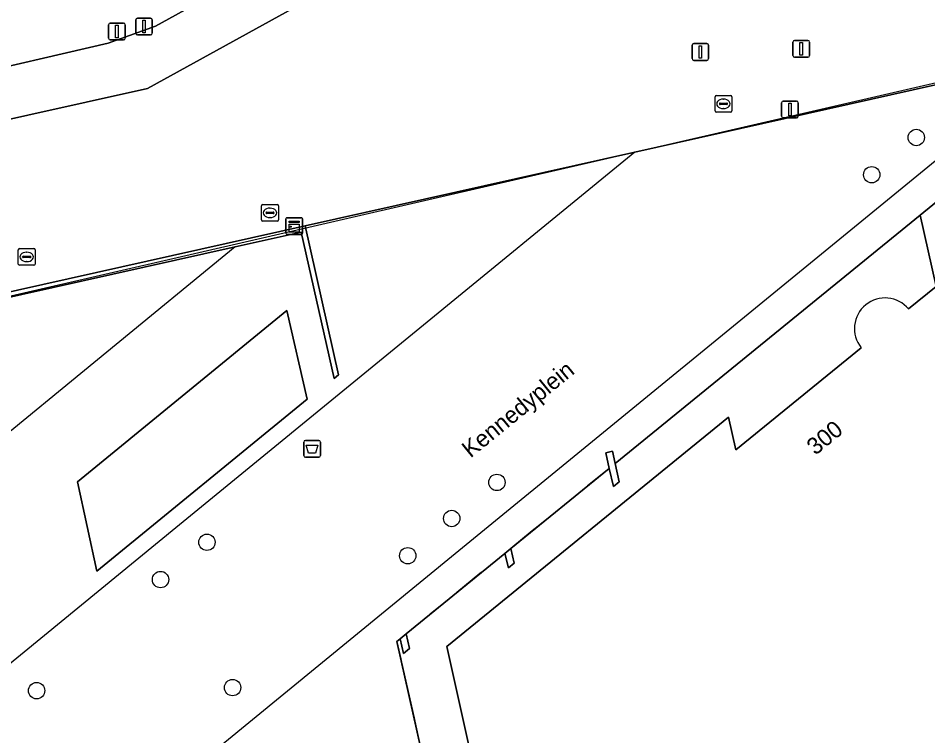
# Model space of a CAD drawing. Extents: x 160806 to 161707, y 383696 to 384148.
# Drawn here: x 161489.3 to 161543.6, y 383912.2 to 383955 of the extents above; entities that cross this region are included whole.
import ezdxf

# ---------------------------------------------------------------- set-up
doc = ezdxf.new("R2010")
doc.units = 0
for name, color, linetype in [('IMGEO_Afvalbak', 7, 'Continuous'), ('IMGEO_Berm_open', 7, 'Continuous'), ('IMGEO_Boom', 7, 'Continuous'), ('IMGEO_Drukknoppaal', 7, 'Continuous'), ('IMGEO_Kast', 7, 'Continuous'), ('IMGEO_Kolk', 7, 'Continuous'), ('IMGEO_Lijnafwatering', 7, 'Continuous'), ('IMGEO_Muur', 7, 'Continuous'), ('IMGEO_Openbare_ruimte_label', 7, 'Continuous'), ('IMGEO_Pand', 7, 'Continuous'), ('IMGEO_Pand_nummerreeks', 7, 'Continuous'), ('IMGEO_Pand_overbouw', 7, 'Continuous'), ('IMGEO_Rijbaan_lokaal_gesloten', 7, 'Continuous'), ('IMGEO_Rioolput', 7, 'Continuous'), ('IMGEO_Verkeersregelinstallatiepaal', 7, 'Continuous'), ('IMGEO_Voetgangersgebied_open', 7, 'Continuous'), ('IMGEO_Voetpad_open', 7, 'Continuous')]:
    doc.layers.add(name, color=color, linetype=linetype)

msp = doc.modelspace()

# ---------------------------------------------------------------- linework, layer by layer
at = {"layer": 'IMGEO_Afvalbak'}
for p, q in [((161506.372, 383928.933), (161506.372, 383929.733)), ((161506.372, 383929.733), (161506.372, 383928.933)), ((161506.472, 383929.833), (161507.262, 383929.833)), ((161507.262, 383929.833), (161506.472, 383929.833)), ((161507.362, 383929.733), (161507.362, 383928.933)), ((161507.362, 383928.933), (161507.362, 383929.733)), ((161507.262, 383928.833), (161506.472, 383928.833)), ((161506.472, 383928.833), (161507.262, 383928.833))]:
    msp.add_line(p, q, dxfattribs=at)
msp.add_lwpolyline([(161506.515, 383929.547), (161507.219, 383929.547), (161507.07, 383929.077), (161506.664, 383929.077), (161506.515, 383929.547)], dxfattribs=at)
for centre, start, end in [((161506.472, 383929.733), 90, 180), ((161506.472, 383929.733), 90, 180), ((161507.262, 383929.733), 0, 90), ((161507.262, 383929.733), 360, 90), ((161506.472, 383928.933), 180, 270), ((161506.472, 383928.933), 180, 270), ((161507.262, 383928.933), 270, 0), ((161507.262, 383928.933), 270, 0)]:
    msp.add_arc(centre, 0.1, start, end, dxfattribs=at)
at = {"layer": 'IMGEO_Berm_open'}
msp.add_lwpolyline([(161482.764, 383950.802), (161484.817, 383951.25), (161485.579, 383951.426), (161494.69, 383953.527), (161497.52, 383954.56), (161515.493, 383964.453)], dxfattribs=at)
at = {"layer": 'IMGEO_Boom'}
for centre in [(161542.926, 383947.907), (161540.266, 383945.685), (161517.898, 383927.324), (161515.202, 383925.175), (161500.593, 383923.754), (161512.579, 383922.952), (161497.824, 383921.531), (161502.123, 383915.083), (161490.429, 383914.901)]:
    msp.add_circle(centre, 0.489, dxfattribs=at)
at = {"layer": 'IMGEO_Drukknoppaal'}
for p, q in [((161496.34, 383954.127), (161496.34, 383954.927)), ((161496.34, 383954.927), (161496.34, 383954.127)), ((161496.44, 383955.027), (161497.23, 383955.027)), ((161497.23, 383955.027), (161496.44, 383955.027)), ((161497.33, 383954.927), (161497.33, 383954.127)), ((161497.33, 383954.127), (161497.33, 383954.927)), ((161497.23, 383954.027), (161496.44, 383954.027)), ((161496.44, 383954.027), (161497.23, 383954.027))]:
    msp.add_line(p, q, dxfattribs=at)
msp.add_lwpolyline([(161496.76, 383954.902), (161496.91, 383954.902), (161496.91, 383954.152), (161496.76, 383954.152), (161496.76, 383954.902)], dxfattribs=at)
for centre, start, end in [((161496.44, 383954.927), 90, 180), ((161496.44, 383954.927), 90, 180), ((161497.23, 383954.927), 0, 90), ((161497.23, 383954.927), 360, 90), ((161496.44, 383954.127), 180, 270), ((161496.44, 383954.127), 180, 270), ((161497.23, 383954.127), 270, 0), ((161497.23, 383954.127), 270, 0)]:
    msp.add_arc(centre, 0.1, start, end, dxfattribs=at)
at = {"layer": 'IMGEO_Kast'}
for p, q in [((161505.305, 383942.198), (161505.305, 383943.039)), ((161505.305, 383943.039), (161505.305, 383942.198)), ((161505.38, 383943.123), (161506.221, 383943.123)), ((161506.221, 383943.123), (161505.38, 383943.123)), ((161506.305, 383943.048), (161506.305, 383942.207)), ((161506.305, 383942.207), (161506.305, 383943.048)), ((161506.23, 383942.123), (161505.389, 383942.123)), ((161505.389, 383942.123), (161506.23, 383942.123))]:
    msp.add_line(p, q, dxfattribs=at)
for points in [[(161505.5, 383942.913), (161506.1, 383942.913), (161506.1, 383942.828), (161505.5, 383942.828), (161505.5, 383942.913)], [(161505.5, 383942.738), (161506.1, 383942.738), (161506.1, 383942.249), (161505.5, 383942.249), (161505.5, 383942.738)]]:
    msp.add_lwpolyline(points, dxfattribs=at)
msp.add_circle((161505.584, 383942.587), 0.0377, dxfattribs=at)
for centre, start, end in [((161505.383, 383943.045), 92.4484, 184.2845), ((161505.383, 383943.045), 92.4484, 184.2845), ((161506.227, 383943.045), 2.4484, 94.2845), ((161506.227, 383943.045), 2.4484, 94.2845), ((161505.383, 383942.201), 182.4484, 274.2845), ((161505.383, 383942.201), 182.4484, 274.2845), ((161506.227, 383942.201), 272.4484, 4.2845), ((161506.227, 383942.201), 272.4484, 4.2845)]:
    msp.add_arc(centre, 0.0779, start, end, dxfattribs=at)
at = {"layer": 'IMGEO_Kolk'}
for p, q in [((161503.856, 383942.985), (161503.856, 383943.837)), ((161503.931, 383943.911), (161504.783, 383943.911)), ((161504.857, 383943.837), (161504.857, 383942.985)), ((161504.115, 383943.405), (161504.115, 383943.417)), ((161504.553, 383943.368), (161504.155, 383943.368)), ((161504.158, 383943.454), (161504.556, 383943.454)), ((161504.344, 383943.691), (161504.369, 383943.691)), ((161504.599, 383943.417), (161504.599, 383943.405)), ((161504.783, 383942.911), (161503.931, 383942.911)), ((161504.367, 383943.131), (161504.342, 383943.131))]:
    msp.add_line(p, q, dxfattribs=at)
for points in [[(161503.856, 383942.985), (161503.856, 383943.837)], [(161503.931, 383943.911), (161504.783, 383943.911)], [(161504.857, 383943.837), (161504.857, 383942.985)], [(161504.783, 383942.911), (161503.931, 383942.911)]]:
    msp.add_lwpolyline(points, dxfattribs=at)
for centre, radius, start, end in [((161503.933, 383943.835), 0.0765, 91.552, 178.448), ((161503.933, 383943.835), 0.0765, 91.552, 178.448), ((161504.781, 383943.835), 0.0765, 1.552, 88.448), ((161504.781, 383943.835), 0.0765, 1.552, 88.448), ((161504.155, 383943.414), 0.0403, 85.8775, 175.7526), ((161504.152, 383943.404), 0.0366, 178.938, 274.7102), ((161504.556, 383943.411), 0.043, 264.8664, 352.4533), ((161504.56, 383943.416), 0.0386, 1.7309, 96.639), ((161503.933, 383942.987), 0.0765, 181.552, 268.448), ((161503.933, 383942.987), 0.0765, 181.552, 268.448), ((161504.781, 383942.987), 0.0765, 271.552, 358.448), ((161504.781, 383942.987), 0.0765, 271.552, 358.448)]:
    msp.add_arc(centre, radius, start, end, dxfattribs=at)
for centre, major_axis, ratio, start_param, end_param in [((161504.343, 383943.411), (-0.387, 0.002), 0.722429, 4.712389, 7.853982), ((161504.368, 383943.411), (-0.39, 0.002), 0.717154, 1.570796, 4.712389)]:
    msp.add_ellipse(centre, major_axis=major_axis, ratio=ratio, start_param=start_param, end_param=end_param, dxfattribs=at)
at = {"layer": 'IMGEO_Lijnafwatering'}
for points in [[(161551.704, 383952.753), (161533.558, 383937.906)], [(161526.128, 383947.032), (161512.429, 383935.821)], [(161502.28, 383941.387), (161486.939, 383928.817)], [(161533.558, 383937.906), (161515.412, 383923.059)], [(161512.429, 383935.821), (161498.731, 383924.609)], [(161498.731, 383924.609), (161485.032, 383913.398)], [(161515.412, 383923.059), (161497.266, 383908.212)]]:
    msp.add_lwpolyline(points, dxfattribs=at)
at = {"layer": 'IMGEO_Muur'}
msp.add_lwpolyline([(161454.756, 383931.084), (161454.819, 383930.799), (161476.856, 383935.709), (161477.167, 383934.318), (161484.378, 383936.019), (161484.102, 383937.319), (161502.28, 383941.387), (161506.222, 383942.268), (161508.183, 383933.535), (161508.439, 383933.738), (161506.454, 383942.63)], close=True, dxfattribs=at)
at = {"layer": 'IMGEO_Pand'}
msp.add_lwpolyline([(161539.638, 383935.367), (161532.156, 383929.275), (161531.72, 383931.221), (161514.903, 383917.532), (161521.152, 383889.432), (161518.425, 383888.826), (161522.234, 383871.748), (161522.889, 383868.814), (161526.561, 383852.352), (161548.06, 383857.157), (161555.04, 383858.718), (161562.148, 383860.307), (161569.113, 383861.863), (161576.544, 383863.524), (161577.028, 383863.632), (161563.33, 383924.497), (161562.871, 383924.395), (161556.299, 383953.974), (161555.972, 383953.708), (161543.162, 383943.281), (161544.114, 383939.013), (161542.463, 383937.675)], dxfattribs=at)
for points in [[(161524.849, 383927.077), (161525.203, 383927.357), (161524.957, 383928.451), (161524.791, 383929.187), (161524.393, 383929.092), (161524.603, 383928.164)], [(161518.585, 383922.232), (161518.924, 383922.501), (161518.722, 383923.384), (161518.377, 383923.091)], [(161512.128, 383917.99), (161512.33, 383917.119), (161512.682, 383917.413), (161512.48, 383918.284)]]:
    msp.add_lwpolyline(points, close=True, dxfattribs=at)
msp.add_arc((161541.06, 383936.509), 1.824, 39.719, 218.778, dxfattribs=at)
at = {"layer": 'IMGEO_Pand_overbouw'}
msp.add_lwpolyline([(161576.544, 383863.524), (161556.299, 383953.974), (161403.923, 383918.874), (161417.58, 383859.039), (161456.542, 383836.683)], close=True, dxfattribs=at)
for points in [[(161542.463, 383937.675), (161544.114, 383939.013), (161543.162, 383943.281), (161524.957, 383928.451), (161525.203, 383927.357), (161524.849, 383927.077), (161524.603, 383928.164), (161523.307, 383927.113), (161523.125, 383926.96), (161521.751, 383925.839), (161521.569, 383925.688), (161520.187, 383924.579), (161520.009, 383924.429), (161518.722, 383923.384), (161518.924, 383922.501), (161518.585, 383922.232), (161518.377, 383923.091), (161517.073, 383922.029), (161516.886, 383921.882), (161515.513, 383920.754), (161515.329, 383920.601), (161513.944, 383919.481), (161513.761, 383919.329), (161512.48, 383918.284), (161512.682, 383917.413), (161512.33, 383917.119), (161512.128, 383917.99)], [(161521.152, 383889.432), (161514.903, 383917.532), (161531.72, 383931.221), (161532.156, 383929.275), (161539.638, 383935.367)], [(161512.128, 383917.99), (161511.932, 383917.834), (161512.164, 383916.794), (161512.207, 383916.608), (161512.559, 383915.03), (161512.602, 383914.843), (161512.953, 383913.273), (161512.995, 383913.087), (161513.344, 383911.529)]]:
    msp.add_lwpolyline(points, dxfattribs=at)
msp.add_arc((161541.06, 383936.509), 1.824, 39.719, 218.778, dxfattribs=at)
at = {"layer": 'IMGEO_Rijbaan_lokaal_gesloten'}
for points in [[(161515.493, 383964.453), (161497.52, 383954.56), (161494.69, 383953.527), (161485.579, 383951.426), (161486.216, 383948.419), (161497.049, 383950.841), (161515.872, 383961.211)], [(161515.872, 383961.211), (161497.049, 383950.841), (161486.216, 383948.419), (161479.851, 383946.996), (161471.217, 383945.134)], [(161454.078, 383945.065), (161451.898, 383943.873), (161452.563, 383940.896), (161454.756, 383931.084), (161506.454, 383942.63), (161526.128, 383947.032), (161551.704, 383952.753), (161555.972, 383953.708), (161556.299, 383953.974), (161562.871, 383924.395), (161563.33, 383924.497), (161577.028, 383863.632), (161576.544, 383863.524), (161578.534, 383854.609), (161578.911, 383853.047), (161586.966, 383854.859), (161586.942, 383854.966), (161586.702, 383856.038), (161585.178, 383862.774), (161563.858, 383956.995)]]:
    msp.add_lwpolyline(points, dxfattribs=at)
at = {"layer": 'IMGEO_Rioolput'}
for p, q in [((161530.915, 383949.49), (161530.915, 383950.342)), ((161530.99, 383950.416), (161531.842, 383950.416)), ((161531.916, 383950.342), (161531.916, 383949.49)), ((161531.174, 383949.91), (161531.174, 383949.922)), ((161531.612, 383949.873), (161531.214, 383949.873)), ((161531.217, 383949.959), (161531.615, 383949.959)), ((161531.403, 383950.196), (161531.428, 383950.196)), ((161531.658, 383949.922), (161531.658, 383949.91)), ((161531.842, 383949.416), (161530.99, 383949.416)), ((161531.426, 383949.636), (161531.401, 383949.636)), ((161489.335, 383940.355), (161489.335, 383941.207)), ((161489.41, 383941.281), (161490.262, 383941.281)), ((161490.336, 383941.207), (161490.336, 383940.355)), ((161489.594, 383940.775), (161489.594, 383940.787)), ((161490.032, 383940.738), (161489.634, 383940.738)), ((161489.637, 383940.824), (161490.035, 383940.824)), ((161489.823, 383941.061), (161489.848, 383941.061)), ((161490.078, 383940.787), (161490.078, 383940.775)), ((161490.262, 383940.281), (161489.41, 383940.281)), ((161489.846, 383940.501), (161489.821, 383940.501))]:
    msp.add_line(p, q, dxfattribs=at)
for points in [[(161530.915, 383949.49), (161530.915, 383950.342)], [(161530.99, 383950.416), (161531.842, 383950.416)], [(161531.916, 383950.342), (161531.916, 383949.49)], [(161531.842, 383949.416), (161530.99, 383949.416)], [(161489.335, 383940.355), (161489.335, 383941.207)], [(161489.41, 383941.281), (161490.262, 383941.281)], [(161490.336, 383941.207), (161490.336, 383940.355)], [(161490.262, 383940.281), (161489.41, 383940.281)]]:
    msp.add_lwpolyline(points, dxfattribs=at)
for centre, radius, start, end in [((161530.992, 383950.34), 0.0765, 91.552, 178.448), ((161530.992, 383950.34), 0.0765, 91.552, 178.448), ((161531.84, 383950.34), 0.0765, 1.552, 88.448), ((161531.84, 383950.34), 0.0765, 1.552, 88.448), ((161531.214, 383949.919), 0.0403, 85.8775, 175.7526), ((161531.211, 383949.909), 0.0366, 178.938, 274.7102), ((161531.615, 383949.916), 0.043, 264.8664, 352.4533), ((161531.619, 383949.921), 0.0386, 1.7309, 96.639), ((161530.992, 383949.492), 0.0765, 181.552, 268.448), ((161530.992, 383949.492), 0.0765, 181.552, 268.448), ((161531.84, 383949.492), 0.0765, 271.552, 358.448), ((161531.84, 383949.492), 0.0765, 271.552, 358.448), ((161489.412, 383941.205), 0.0765, 91.552, 178.448), ((161489.412, 383941.205), 0.0765, 91.552, 178.448), ((161490.26, 383941.205), 0.0765, 1.552, 88.448), ((161490.26, 383941.205), 0.0765, 1.552, 88.448), ((161489.634, 383940.784), 0.0403, 85.8775, 175.7526), ((161489.631, 383940.774), 0.0366, 178.938, 274.7102), ((161490.035, 383940.781), 0.043, 264.8664, 352.4533), ((161490.039, 383940.786), 0.0386, 1.7309, 96.639), ((161489.412, 383940.357), 0.0765, 181.552, 268.448), ((161489.412, 383940.357), 0.0765, 181.552, 268.448), ((161490.26, 383940.357), 0.0765, 271.552, 358.448), ((161490.26, 383940.357), 0.0765, 271.552, 358.448)]:
    msp.add_arc(centre, radius, start, end, dxfattribs=at)
for centre, major_axis, ratio, start_param, end_param in [((161531.402, 383949.916), (-0.387, 0.002), 0.722429, 4.712389, 7.853982), ((161531.427, 383949.916), (-0.39, 0.002), 0.717154, 1.570796, 4.712389), ((161489.822, 383940.781), (-0.387, 0.002), 0.722429, 4.712389, 7.853982), ((161489.847, 383940.781), (-0.39, 0.002), 0.717154, 1.570796, 4.712389)]:
    msp.add_ellipse(centre, major_axis=major_axis, ratio=ratio, start_param=start_param, end_param=end_param, dxfattribs=at)
at = {"layer": 'IMGEO_Verkeersregelinstallatiepaal'}
for p, q in [((161494.825, 383954.73), (161495.615, 383954.73)), ((161495.615, 383954.73), (161494.825, 383954.73)), ((161494.725, 383953.83), (161494.725, 383954.63)), ((161494.725, 383954.63), (161494.725, 383953.83)), ((161495.715, 383954.63), (161495.715, 383953.83)), ((161495.715, 383953.83), (161495.715, 383954.63)), ((161495.615, 383953.73), (161494.825, 383953.73)), ((161494.825, 383953.73), (161495.615, 383953.73)), ((161535.566, 383952.797), (161535.566, 383953.597)), ((161535.566, 383953.597), (161535.566, 383952.797)), ((161535.666, 383953.697), (161536.456, 383953.697)), ((161536.456, 383953.697), (161535.666, 383953.697)), ((161536.556, 383953.597), (161536.556, 383952.797)), ((161536.556, 383952.797), (161536.556, 383953.597)), ((161529.542, 383952.612), (161529.542, 383953.412)), ((161529.542, 383953.412), (161529.542, 383952.612)), ((161529.642, 383953.512), (161530.432, 383953.512)), ((161530.432, 383953.512), (161529.642, 383953.512)), ((161530.532, 383953.412), (161530.532, 383952.612)), ((161530.532, 383952.612), (161530.532, 383953.412)), ((161530.432, 383952.512), (161529.642, 383952.512)), ((161529.642, 383952.512), (161530.432, 383952.512)), ((161536.456, 383952.697), (161535.666, 383952.697)), ((161535.666, 383952.697), (161536.456, 383952.697)), ((161534.891, 383949.181), (161534.891, 383949.981)), ((161534.891, 383949.981), (161534.891, 383949.181)), ((161534.991, 383950.081), (161535.781, 383950.081)), ((161535.781, 383950.081), (161534.991, 383950.081)), ((161535.881, 383949.981), (161535.881, 383949.181)), ((161535.881, 383949.181), (161535.881, 383949.981)), ((161535.781, 383949.081), (161534.991, 383949.081)), ((161534.991, 383949.081), (161535.781, 383949.081))]:
    msp.add_line(p, q, dxfattribs=at)
for points in [[(161495.145, 383954.605), (161495.295, 383954.605), (161495.295, 383953.855), (161495.145, 383953.855), (161495.145, 383954.605)], [(161535.986, 383953.572), (161536.136, 383953.572), (161536.136, 383952.822), (161535.986, 383952.822), (161535.986, 383953.572)], [(161529.962, 383953.387), (161530.112, 383953.387), (161530.112, 383952.637), (161529.962, 383952.637), (161529.962, 383953.387)], [(161535.311, 383949.956), (161535.461, 383949.956), (161535.461, 383949.206), (161535.311, 383949.206), (161535.311, 383949.956)]]:
    msp.add_lwpolyline(points, dxfattribs=at)
for centre, start, end in [((161494.825, 383954.63), 90, 180), ((161494.825, 383954.63), 90, 180), ((161495.615, 383954.63), 0, 90), ((161495.615, 383954.63), 360, 90), ((161494.825, 383953.83), 180, 270), ((161494.825, 383953.83), 180, 270), ((161495.615, 383953.83), 270, 0), ((161495.615, 383953.83), 270, 0), ((161535.666, 383953.597), 90, 180), ((161535.666, 383953.597), 90, 180), ((161536.456, 383953.597), 0, 90), ((161536.456, 383953.597), 360, 90), ((161529.642, 383953.412), 90, 180), ((161529.642, 383953.412), 90, 180), ((161530.432, 383953.412), 0, 90), ((161530.432, 383953.412), 360, 90), ((161529.642, 383952.612), 180, 270), ((161529.642, 383952.612), 180, 270), ((161530.432, 383952.612), 270, 0), ((161530.432, 383952.612), 270, 0), ((161535.666, 383952.797), 180, 270), ((161535.666, 383952.797), 180, 270), ((161536.456, 383952.797), 270, 0), ((161536.456, 383952.797), 270, 0), ((161534.991, 383949.981), 90, 180), ((161534.991, 383949.981), 90, 180), ((161535.781, 383949.981), 0, 90), ((161535.781, 383949.981), 360, 90), ((161534.991, 383949.181), 180, 270), ((161534.991, 383949.181), 180, 270), ((161535.781, 383949.181), 270, 0), ((161535.781, 383949.181), 270, 0)]:
    msp.add_arc(centre, 0.1, start, end, dxfattribs=at)
at = {"layer": 'IMGEO_Voetgangersgebied_open'}
for points in [[(161511.932, 383917.834), (161512.128, 383917.99), (161512.48, 383918.284), (161518.377, 383923.091), (161518.722, 383923.384), (161524.603, 383928.164), (161524.393, 383929.092), (161524.791, 383929.187), (161524.957, 383928.451), (161543.162, 383943.281), (161555.972, 383953.708)], [(161551.704, 383952.753), (161526.128, 383947.032), (161506.454, 383942.63), (161508.439, 383933.738), (161508.183, 383933.535), (161506.222, 383942.268), (161502.28, 383941.387), (161484.102, 383937.319)], [(161454.649, 383859.314), (161452.306, 383869.965), (161465.897, 383881.096), (161472.218, 383886.284), (161492.387, 383902.807), (161497.417, 383906.928), (161499.226, 383908.41), (161507.57, 383871.236), (161502.965, 383867.464), (161522.234, 383871.748), (161518.425, 383888.826), (161511.932, 383917.834)]]:
    msp.add_lwpolyline(points, dxfattribs=at)
msp.add_lwpolyline([(161494.03, 383922.036), (161492.872, 383927.352), (161505.371, 383937.593), (161506.572, 383932.289)], close=True, dxfattribs=at)
at = {"layer": 'IMGEO_Voetpad_open'}
msp.add_lwpolyline([(161542.463, 383937.675), (161544.114, 383939.013), (161543.162, 383943.281), (161524.957, 383928.451), (161525.203, 383927.357), (161524.849, 383927.077), (161524.603, 383928.164), (161518.722, 383923.384), (161518.924, 383922.501), (161518.585, 383922.232), (161518.377, 383923.091), (161512.48, 383918.284), (161512.682, 383917.413), (161512.33, 383917.119), (161512.128, 383917.99), (161511.932, 383917.834), (161518.425, 383888.826), (161521.152, 383889.432), (161514.903, 383917.532), (161531.72, 383931.221), (161532.156, 383929.275), (161539.638, 383935.367)], dxfattribs=at)
msp.add_lwpolyline([(161494.03, 383922.036), (161506.572, 383932.289), (161505.371, 383937.593), (161492.872, 383927.352)], close=True, dxfattribs=at)
msp.add_arc((161541.06, 383936.509), 1.824, 39.719, 218.778, dxfattribs=at)

# ---------------------------------------------------------------- texts
at = {"layer": 'IMGEO_Openbare_ruimte_label'}
msp.add_text('Kennedyplein', height=1, rotation=39.1967, dxfattribs=at).set_placement((161516.324, 383928.749))
at = {"layer": 'IMGEO_Pand_nummerreeks'}
msp.add_text('300', height=1, rotation=39.1532, dxfattribs=at).set_placement((161536.904, 383928.911))

doc.saveas('drawing.dxf')
